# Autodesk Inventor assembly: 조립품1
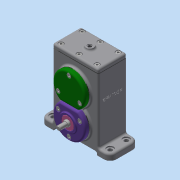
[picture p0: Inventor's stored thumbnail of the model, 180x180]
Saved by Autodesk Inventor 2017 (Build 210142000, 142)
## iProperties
Part Number: 조립품1
Material: 일반
Document SubType Name: Assembly
Designer: mrc
Mass: 1460.95 g
Surface Area: 1575.48 cm^2
Volume: 385.032 cm^3
Density: 3.79437 g/cm^3
Author: mrc
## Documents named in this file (24)
- C:\Users\mrc\Desktop\600506V1051\답안조립품.iam
- C:\Users\mrc\Desktop\600506V1051\본체.ipt
- C:\Users\mrc\Desktop\600506V1051\개스킷 A.ipt
- C:\Users\mrc\Desktop\600506V1051\개스킷 B.ipt
- C:\Users\mrc\Desktop\600506V1051\개스킷 C.ipt
- C:\Users\mrc\Desktop\600506V1051\베어링 6001.ipt
- 베어링 6001.ipt
- C:\Users\mrc\Desktop\600506V1051\베어링 6002.ipt
- 베어링 6002.ipt
- C:\Users\mrc\Desktop\600506V1051\볼트 M4.ipt
- C:\Users\mrc\Desktop\600506V1051\스퍼기어 A.ipt
- C:\Users\mrc\Desktop\600506V1051\스퍼기어 B.ipt
- C:\Users\mrc\Desktop\600506V1051\오일 실 10 20 7.ipt
- C:\Users\mrc\Desktop\600506V1051\오일 실 12 22 7.ipt
- C:\Users\mrc\Desktop\600506V1051\축 A.ipt
- C:\Users\mrc\Desktop\600506V1051\축 B.ipt
- C:\Users\mrc\Desktop\600506V1051\칼라.ipt
- C:\Users\mrc\Desktop\600506V1051\커버 A.ipt
- C:\Users\mrc\Desktop\600506V1051\커버 B.ipt
- C:\Users\mrc\Desktop\600506V1051\커버 C.ipt
- C:\Users\mrc\Desktop\600506V1051\커버 E.ipt
- C:\Users\mrc\Desktop\600506V1051\키 4 x 4 x 12.ipt
- C:\Users\mrc\Desktop\600506V1051\키 5 x 5 x 12.ipt
- C:\Users\mrc\Desktop\600506V1051\커버 D.ipt
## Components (5 placed, 3 different names)
1. 개스킷 A:1
2. 개스킷 B:1
3. 개스킷 C:1
4. 개스킷 B:2
5. 개스킷 B:3
